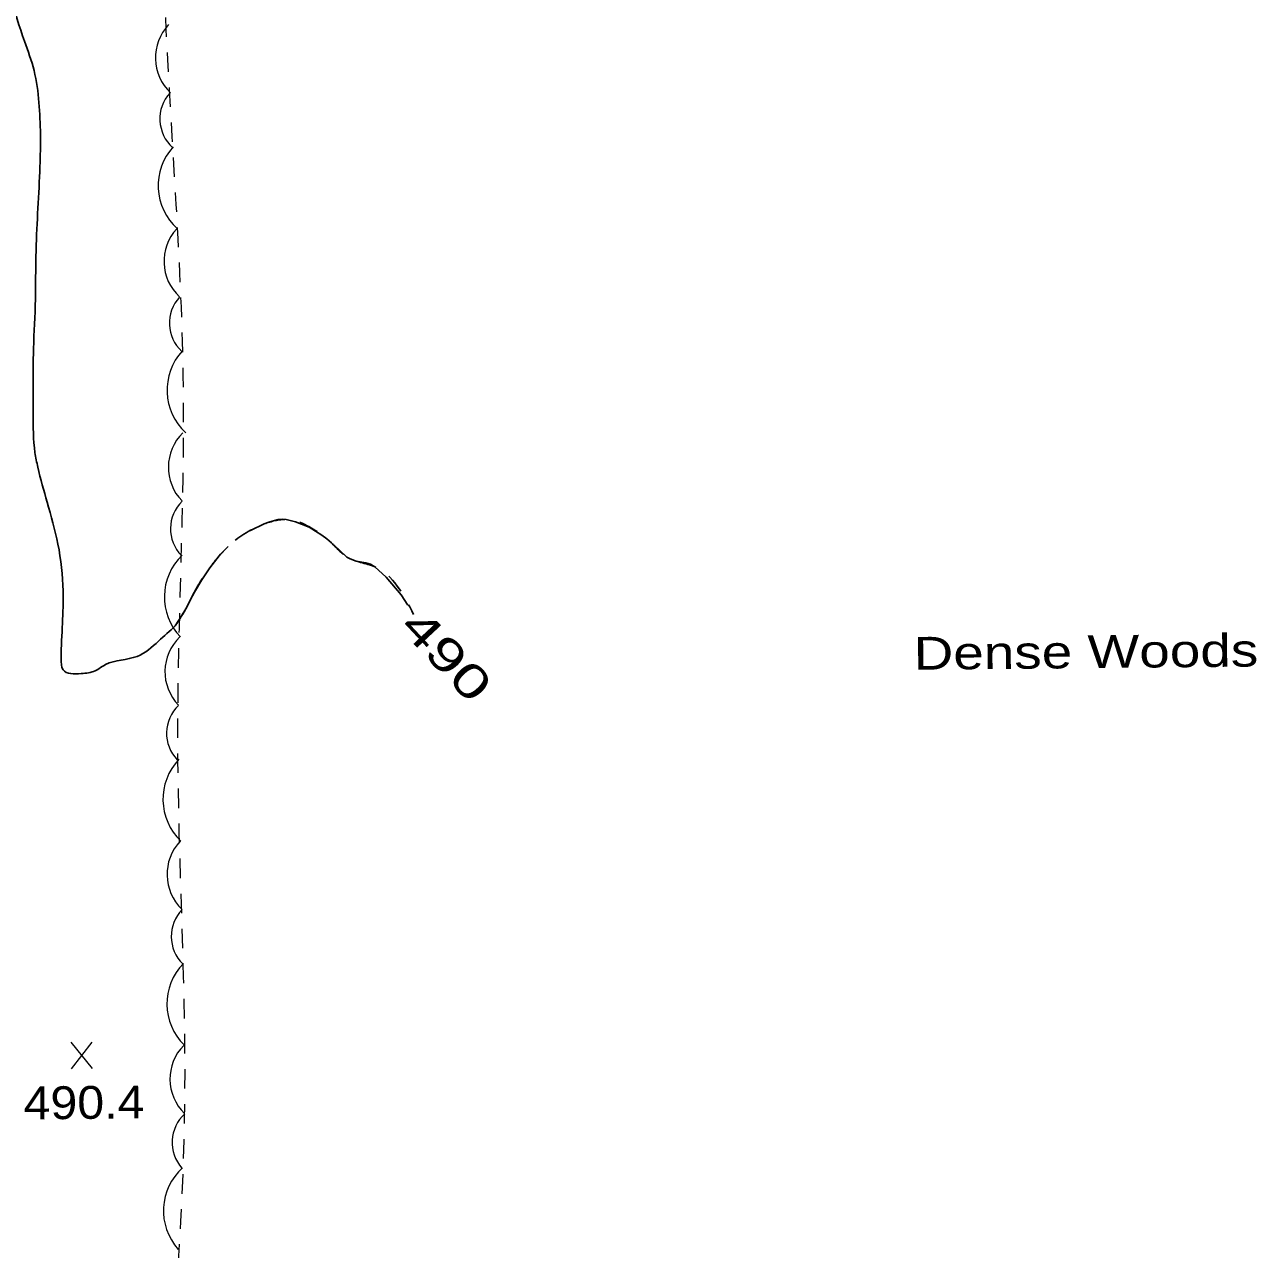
# Model space of a CAD drawing. Extents: x 2362213 to 2366494, y 6968794 to 6978110.
# Drawn here: x 2364559.9 to 2364740.1, y 6971343.7 to 6971522.8 of the extents above; entities that cross this region are included whole.
import ezdxf
from ezdxf.enums import TextEntityAlignment as Align

# ---------------------------------------------------------------- set-up
doc = ezdxf.new("R2010")
doc.units = 0
doc.header["$LTSCALE"] = 1.9
doc.linetypes.add('SHORT_DASHED', pattern=[2.7, 1.5, -1.2])
for name, color, linetype, lineweight in [('29', 7, 'Continuous', 13), ('31', 7, 'Continuous', 25), ('32', 7, 'Continuous', 25)]:
    doc.layers.add(name, color=color, linetype=linetype, lineweight=lineweight)

msp = doc.modelspace()

# ---------------------------------------------------------------- linework, layer by layer
at = {"layer": '29'}
for centre, radius, start, end in [((2364586.116, 6971517.944), 7.053, 136.48006, 226.48006), ((2364585.351, 6971509.016), 5.637, 137.83484, 227.83484), ((2364587.923, 6971499.235), 8.46, 137.83484, 227.83484), ((2364587.373, 6971488.175), 7.053, 137.32977, 227.32977), ((2364586.742, 6971479.143), 5.637, 137.32977, 227.32977), ((2364589.227, 6971469.34), 8.46, 137.32977, 227.32977), ((2364588.013, 6971458.059), 7.053, 134.29925, 224.29925), ((2364586.906, 6971449.073), 5.637, 134.29925, 224.29925), ((2364588.829, 6971439.101), 8.46, 133.8125, 223.8125), ((2364587.515, 6971428.151), 7.053, 133.8125, 223.8125), ((2364586.331, 6971419.175), 5.637, 133.8125, 223.8125), ((2364588.631, 6971409.513), 8.46, 136.41026, 226.41026), ((2364587.814, 6971398.515), 7.053, 136.41026, 226.41026), ((2364587.023, 6971389.439), 5.637, 135.62068, 225.62068), ((2364589.215, 6971379.565), 8.46, 135.62068, 225.62068), ((2364588.246, 6971368.58), 7.053, 135.62068, 225.62068), ((2364587.145, 6971359.32), 5.637, 131.94136, 221.94136), ((2364588.699, 6971349.326), 8.46, 131.94136, 221.94136)]:
    msp.add_arc(centre, radius, start, end, dxfattribs=at)
at = {"layer": '29', "linetype": 'SHORT_DASHED'}
msp.add_spline([(2364577.69, 6971075.047), (2364579.29, 6971120.184), (2364580.17, 6971165.405), (2364577.6, 6971211.582), (2364578.72, 6971259.895), (2364580.684, 6971315.076), (2364583.342, 6971362.574), (2364582.348, 6971418.658), (2364583.179, 6971469.038), (2364581.378, 6971508.953), (2364580.351, 6971579.056), (2364585.114, 6971632.334), (2364584.87, 6971699.884), (2364582.326, 6971774.844), (2364585.046, 6971827.382), (2364586.299, 6971874.516), (2364587.992, 6971886.814), (2364587.862, 6971909.833), (2364589.094, 6971931.726), (2364587.912, 6971940.364)], degree=3, dxfattribs=at)
at = {"layer": '31', "lineweight": 13}
for p, q in [((2364569.861, 6971370.116), (2364566.744, 6971373.967)), ((2364566.781, 6971370.086), (2364569.824, 6971373.996))]:
    msp.add_line(p, q, dxfattribs=at)
at = {"layer": '31'}
msp.add_spline([(2364553.687, 6971687.457), (2364553.954, 6971683.649), (2364554.585, 6971674.055), (2364554.856, 6971667.607), (2364554.477, 6971655.993), (2364554.052, 6971647.029), (2364553.672, 6971634.474), (2364553.66, 6971623.124), (2364553.148, 6971609.638), (2364552.661, 6971598.863), (2364552.7, 6971587.403), (2364553.486, 6971578.36), (2364554.117, 6971568.775), (2364554.46, 6971562.249), (2364554.423, 6971548.227), (2364555.171, 6971540.014), (2364556.103, 6971533.583), (2364557.837, 6971526.879), (2364559.929, 6971520.368), (2364561.32, 6971516.082), (2364562.034, 6971511.428), (2364562.183, 6971502.058), (2364561.61, 6971489.823), (2364561.487, 6971481.681), (2364561.215, 6971474.548), (2364561.187, 6971465.918), (2364561.452, 6971460.2), (2364561.872, 6971458.064), (2364563.232, 6971452.976), (2364564.81, 6971446.832), (2364565.565, 6971439.979), (2364565.279, 6971430.105), (2364565.565, 6971428.427), (2364568.201, 6971427.882), (2364570.267, 6971428.302), (2364571.758, 6971429.196), (2364576.386, 6971430.4), (2364579.525, 6971432.63), (2364581.964, 6971434.854)], degree=3, dxfattribs=at)
at = {"layer": '32'}
for points in [[(2364592.933, 6971448.78), (2364592.973, 6971448.81), (2364594.983, 6971449.778), (2364595.78, 6971450.096), (2364596.997, 6971450.408), (2364597.606, 6971450.453), (2364598.207, 6971450.409), (2364599.57, 6971450.102), (2364601.567, 6971449.312), (2364603.418, 6971448.15), (2364604.124, 6971447.576), (2364604.809, 6971446.993), (2364605.939, 6971445.964), (2364607.079, 6971444.934), (2364607.523, 6971444.649), (2364608.406, 6971444.347), (2364609.848, 6971444.091), (2364610.54, 6971443.877), (2364611.144, 6971443.513), (2364612.829, 6971441.969), (2364615.023, 6971439.4), (2364615.967, 6971437.908)], [(2364581.964, 6971434.854), (2364582.841, 6971436.222), (2364583.658, 6971437.62), (2364584.217, 6971438.716), (2364584.767, 6971439.812), (2364585.841, 6971441.612), (2364587.014, 6971443.353), (2364588.388, 6971445.116), (2364589.695, 6971446.459)]]:
    msp.add_lwpolyline(points, dxfattribs=at)
at = {"layer": '32', "linetype": 'SHORT_DASHED'}
msp.add_spline([(2364581.964, 6971434.854), (2364583.658, 6971437.62), (2364584.767, 6971439.812), (2364587.014, 6971443.353), (2364589.972, 6971446.742), (2364594.983, 6971449.778), (2364598.207, 6971450.409), (2364603.418, 6971448.15), (2364604.809, 6971446.993), (2364607.079, 6971444.934), (2364611.144, 6971443.513), (2364616.831, 6971436.536)], degree=3, dxfattribs=at)

# ---------------------------------------------------------------- texts
at = {"layer": '29', "width": 1.25}
msp.add_text('Dense Woods', height=4.8, rotation=0.546, dxfattribs=at).set_placement((2364689.97, 6971428.442))
at = {"layer": '31', "width": 1.45}
msp.add_text(' 490 ', height=4.8, rotation=313.088, dxfattribs=at).set_placement((2364619.897, 6971428.922), align=Align.CENTER)
at = {"layer": '31', "width": 1.1}
msp.add_text('490.4', height=4.8, rotation=0.546, dxfattribs=at).set_placement((2364559.81, 6971362.67))

doc.saveas('drawing.dxf')
